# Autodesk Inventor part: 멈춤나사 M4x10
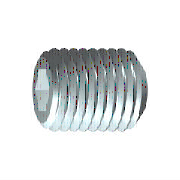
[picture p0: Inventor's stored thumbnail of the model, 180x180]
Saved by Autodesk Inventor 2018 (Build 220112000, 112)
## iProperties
Created: 2012-02
Part Number: 멈춤나사 M4x10
Material: 강철, 연강
Description: 6각 소켓 머리 없는 멈춤 나사
Document SubType Name: Modeling
Standard: KS B 1028
Designer: mduedu
Standards Organization: KS
Language: ko-KR
Size Designation: 납작점M4x10
Categories: <MemberInstance><Categories><Category DisplayName="조임쇠" InternalName="e4da775c-781d-43d5-af7c-5136215cf5a6" Mnemonic="FSTN"><Category DisplayName="볼트" InternalN
Density: 1 g/cm^3
Appearance: 강철
IsCustomPart: 1
Author: mduedu
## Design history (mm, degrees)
sketch "스케치1"
  geometry: L1 (0, 0)-(6.833, 0); L2 (10, 1.155)-(10, 2); L3 (10, 2)-(0, 2); L4 (10, 1.155)-(7.5, 1.155); L5 (7.5, 1.155)-(6.833, 0); L6 (0, -0.4)-(0, 2.4) reference; L7 (0, 2)-(0, 0)
  constraints: 13 end point, 3 parallel, 1 collinear, 1 perpendicular, 1 point on line
  dimensions: "d0" = 2.5 distance of L2.start L4.end (= INTI); "d1" = 60 deg angle of L5 L1; "d2" = 4 diameter of L3 L1 (= NND); "d3" = 2.3094 diameter of L4 L1 (= 1.1547 x SW); "d5" = 10 distance from line of L2 L3.end (= NLG)
revolve "본체" sketch "스케치1" stored, may be unused: angle "d6" = 90 deg
sketch "스케치2"
  geometry: L1 (-0.577, 1)-(0.577, 1); L2 (0.577, 1)-(1.155, 0); L3 (1.155, 0)-(0.577, -1); L4 (0.577, -1)-(-0.577, -1); L5 (-0.577, -1)-(-1.155, 0); L6 (-1.155, 0)-(-0.577, 1); A1 r 1.155 centre (0, 0) between (-0.577, 1) and (0.577, 1) reference; 2 further points
  constraints: 12 end point, 2 point on circle, 1 coincident, 1 horizontal, 11 other
extrude "슬롯" join sketch "스케치2" taper "d9" = 0 deg; stored distance "d21" = 10
workaxis "Work Axis1"
workplane "Work Plane1"
body "Solid1"
chamfer "모따기1" distance "d7" = 0.42941 (= -0.5 x GD1 + 0.5 x NND); stored, may be unused: angle "d8" = 45 deg (= FAWI), second distance "d29" = 0.42941 (= -0.5 x GD1 + 0.5 x NND)
feature "스레드" dims "d11" = 10 (= NLG), "d12" = 0
chamfer "모따기2" distance "d13" = 0.42941 (= -0.5 x GD1 + 0.5 x NND); stored, may be unused: angle "d14" = 45 deg (= FAWI), second distance "d30" = 0.42941 (= -0.5 x GD1 + 0.5 x NND)
other parameters: "NND" = 4 [user parameter; used in 5 equation terms], "NLG" = 10 [user parameter; used in 2 equation terms], "INTI" = 2.5 [user parameter; used in 1 equation term], "FAWI" = 45 deg [user parameter; used in 2 equation terms], "SW" = 2 [user parameter; used in 2 equation terms], "GD1" = 3.14117 (= THREADDIA - 1.2269 x PTC) [user parameter; used in 4 equation terms], "d4" = 0, "FAWI1" = 45 deg [user parameter], "d15" = 0, "d31" = 0, "GUL" = 0.42941 (= 0.61345 x PTC) [user parameter], "SPD" = 2.5 [user parameter], "TPU" = 14.28571 (computed from PTC) [user parameter], "TOA" = 30 deg [user parameter], "THREADDIA" = 4 [user parameter; used in 1 equation term], "PTC" = 0.7 [user parameter; used in 4 equation terms], "GAL" = 0.42941 (= 0.61345 x PTC) [user parameter], "E0" = 2.31 (= 1.155 x SW) [user parameter]
